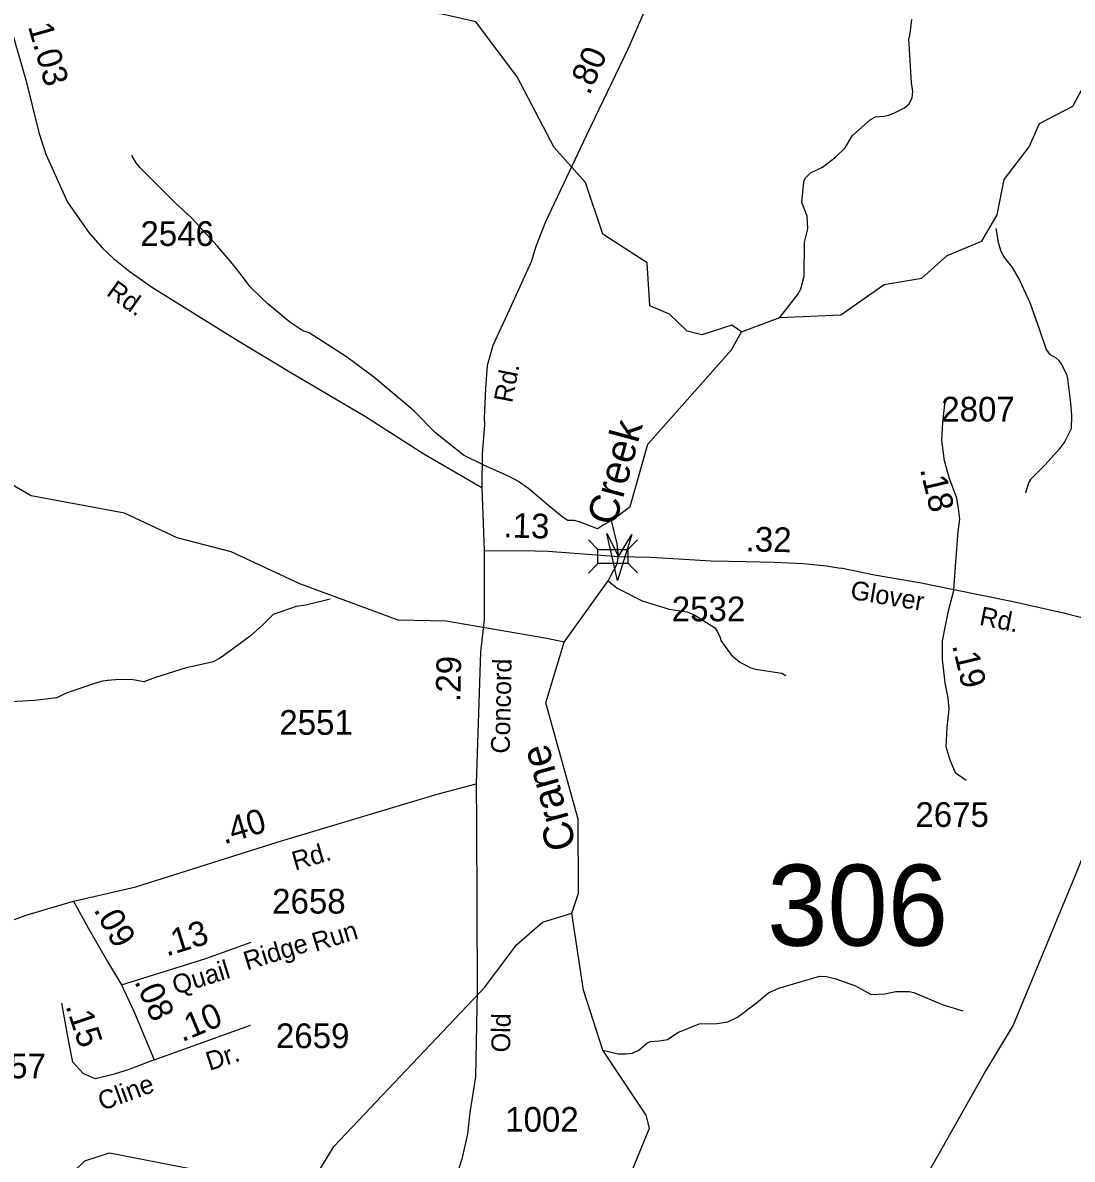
# Model space of a CAD drawing. Extents: x 1473865 to 1648260, y 639067 to 773536.
# Drawn here: x 1551434 to 1556744, y 667690 to 673439 of the extents above; entities that cross this region are included whole.
import ezdxf

# ---------------------------------------------------------------- set-up
doc = ezdxf.new("R2010")
doc.units = 0
for name, color, linetype in [('Exist Hydrographic Creek Single Shore', 7, 'Continuous'), ('Exist Hydrographic Creek Single Shore Label', 7, 'Continuous'), ('Exist Hydrographic Misc Water Feature', 7, 'Continuous'), ('Exist Road Secondary Mileage Hundredths English Label', 7, 'Continuous'), ('Exist Road Secondary Structure Standard Bridge Attributed CELL', 7, 'Continuous'), ('Exist Road Secondary Structure Standard Bridge CELL', 7, 'Continuous'), ('Exist Road Secondary Structure Standard Bridge Number Label', 7, 'Continuous'), ('Exist Road Secondary Type 51 Attributed', 7, 'Continuous'), ('Exist Road Secondary Type 51 Label', 7, 'Continuous'), ('Exist Road Secondary Type 51 Number Label', 7, 'Continuous'), ('Exist Utilities Electrical Transmission Line', 7, 'Continuous')]:
    doc.layers.add(name, color=color, linetype=linetype)

msp = doc.modelspace()

# ---------------------------------------------------------------- linework, layer by layer
at = {"layer": 'Exist Hydrographic Creek Single Shore'}
for p, q in [((1554172.4, 670305.3), (1554085.4, 670323.4)), ((1554063.8, 668889.4), (1554211.3, 668935.7))]:
    msp.add_line(p, q, dxfattribs=at)
for points in [[(1554123, 672807.5), (1553935.4, 673165.7), (1553726.4, 673443.2), (1553556.4, 673481.9), (1553324.4, 673509.6), (1553241.4, 673554), (1553135.4, 673697.3), (1553079.4, 673829.7), (1552890.4, 674027.2), (1552768.5, 674236.4), (1552555.4, 674457.4), (1552482.4, 674583.5), (1552154.5, 674944.7), (1551831.4, 675584.7), (1551686.1, 675837.9), (1551655.2, 675963.3), (1551592.1, 676013.9), (1551494.5, 676431.8), (1551362.4, 676559.2), (1551113.4, 676613.5), (1550907.4, 676732.5)], [(1555070.4, 671875.8), (1555263.5, 671947.4), (1555572.5, 671960.9), (1555791.5, 672114), (1555983.4, 672146.2), (1556110.4, 672261.8), (1556286.5, 672333.7), (1556363.5, 672466.8), (1556399.4, 672646.6), (1556526.5, 672811.5), (1556578.5, 672928.5), (1556746.5, 673017.1), (1556823.5, 673159.9), (1557043.4, 673372.1), (1557481.5, 673698.1), (1557672.5, 673648.3), (1557798.5, 673678.6), (1557883.5, 673834.4), (1557865.7, 674112.6), (1557939.2, 674210.1), (1558074.5, 674332.8), (1558259.5, 674430.8)], [(1554085.4, 670323.4), (1553575.4, 670412.5), (1553333.4, 670417.4), (1552836.4, 670601.4), (1552488.4, 670762.6), (1552214.3, 670833.8), (1551949.4, 670957.3), (1551476.4, 671045.7), (1551087.4, 671270.2), (1550964.3, 671403.9), (1550851.4, 671606.5), (1550744.4, 671726.8), (1550656.3, 671925.5), (1550653.4, 672250.5), (1550520.4, 672853.9), (1550301.4, 673199.7), (1550256.4, 673509.2), (1550159.4, 673727.7), (1550088.4, 673985.2), (1550033.4, 674212.8)], [(1555070.4, 671875.8), (1555021.4, 671909.6), (1554870.4, 671860.2), (1554795.4, 671878.1), (1554705.4, 671965.2), (1554606.5, 672006.6), (1554592.4, 672223.6), (1554369.4, 672369.2), (1554281.5, 672630.3), (1554123, 672807.5)], [(1554172.4, 670305.3), (1554396.2, 670615.8), (1554441.5, 670701.6), (1554447.6, 670738.8), (1554441.6, 670803.2), (1554411.9, 670921.2), (1554507.4, 670991.1), (1554596.4, 671307.7), (1555019.4, 671784.9), (1555070.4, 671875.8)], [(1554211.3, 668935.7), (1554246.4, 669036.7), (1554243.4, 669411), (1554080.5, 669998.5), (1554172.4, 670305.3)], [(1554604.3, 667312.7), (1554582.4, 667464.2), (1554517.4, 667632.9), (1554604.3, 667847.8), (1554588.3, 667913.7), (1554369.6, 668241.2), (1554270.8, 668545.4), (1554211.3, 668935.7)], [(1545869.2, 665457.2), (1546029.2, 665562.3), (1546363.3, 665591.7), (1546740.3, 665718.7), (1547066.3, 665771.2), (1547409.2, 665859.4), (1548036, 665819.7), (1548368.3, 665853.2), (1548861.3, 665984.4), (1549566.3, 666242.6), (1550238.3, 666590.1), (1550751.3, 666888.3), (1551234.3, 667374.3), (1551553.3, 667492.6), (1551748.4, 667682.2), (1551873.3, 667722.4), (1552289.4, 667641.8), (1552916, 667605.3), (1553007.1, 667754.7), (1553771.4, 668560.5), (1553932.4, 668773.9), (1554063.8, 668889.4)]]:
    msp.add_lwpolyline(points, dxfattribs=at)
at = {"layer": 'Exist Hydrographic Misc Water Feature'}
for points in [[(1555263.5, 671947.4), (1555357.9, 672069), (1555370.2, 672092.8), (1555386.9, 672156.6), (1555388.8, 672328.6), (1555405.6, 672396.4), (1555402.3, 672460.5), (1555375, 672528.8), (1555384, 672616.7), (1555388.2, 672640.7), (1555396.4, 672656.5), (1555418.7, 672680.3), (1555481, 672707.6), (1555545.6, 672758.9), (1555594.2, 672806.3), (1555630.9, 672865.9), (1555723.8, 672948.8), (1555748, 672962.5), (1555792.1, 672966), (1555814.1, 672971.8), (1555840.3, 672981.5), (1555894.5, 673008.8), (1555916.8, 673026.6), (1555933.2, 673058.3), (1555937.5, 673090.3), (1555930, 673134.4), (1555916.4, 673358.6), (1555920.5, 673366.5), (1555924.9, 673398.5), (1555931.5, 673454.4)], [(1554095.8, 670994.4), (1553995.2, 671081.8), (1553941.8, 671119), (1553894.1, 671143.8), (1553767, 671201.3), (1553663.8, 671251), (1553521.4, 671363.8), (1553413.2, 671475.1), (1553365.8, 671516.3), (1553209.9, 671646.7), (1553116.9, 671715.8), (1553071.3, 671748.7), (1552883.2, 671869.9), (1552851.4, 671880.4), (1552786, 671923.5), (1552673.4, 672016.9), (1552643.8, 672045.4), (1552584.7, 672102.4), (1552551.3, 672149), (1552494.5, 672219.9), (1552420, 672309.2), (1552288.2, 672451.4), (1552205.3, 672527), (1552028, 672705.3), (1552008.4, 672729.5), (1551988.9, 672760.3), (1551987, 672768.5)], [(1556356.6, 672398.7), (1556369.2, 672329.2), (1556380.8, 672289.1), (1556396.4, 672256.9), (1556439.8, 672200.4), (1556477.1, 672135.9), (1556529.9, 672023.3), (1556576.4, 671890.8), (1556611.3, 671786.4), (1556629, 671762.1), (1556658.8, 671745.8), (1556674.7, 671731.6), (1556688.5, 671713.4), (1556713.9, 671661.1), (1556719.6, 671637.1), (1556732.5, 671528.9), (1556740.8, 671453.5), (1556738.9, 671384.8), (1556706.2, 671321.2), (1556677.7, 671281.5), (1556606.9, 671202.3), (1556532, 671129.2), (1556521.8, 671111.3), (1556507.2, 671059.5)], [(1554411.9, 670921.2), (1554370, 670897.2), (1554342.6, 670879.3), (1554290.1, 670899.6), (1554248.4, 670913.9), (1554223.4, 670921.1), (1554192.4, 670921.1), (1554162.6, 670940.2), (1554095.8, 670994.4)], [(1554396.2, 670615.8), (1554441.1, 670579.5), (1554568.4, 670514), (1554704, 670472.4), (1554795.9, 670459.4), (1554834.9, 670442.5), (1554933, 670379.7), (1554946.9, 670361.6), (1554962.5, 670329.4), (1554966.3, 670313.4), (1555017.6, 670240.8), (1555061.2, 670204.2), (1555116.8, 670175.6), (1555140.8, 670169.3), (1555273.8, 670148.1), (1555295, 670137.6)], [(1552989.9, 670523.6), (1552865.5, 670493.2), (1552817.3, 670486), (1552700.8, 670445.7), (1552647.8, 670392.6), (1552584.9, 670335.6), (1552451.3, 670238.2), (1552428.9, 670222.2), (1552396.8, 670206.5), (1552316.4, 670187.6), (1552260.3, 670176.4), (1552105.3, 670127), (1552047, 670104.4), (1551983.3, 670117.2), (1551903.3, 670114.7), (1551863.2, 670111.4), (1551839.1, 670107.7), (1551806.9, 670100.2), (1551654, 670048.3), (1551605.6, 670024.7), (1551493.3, 670010.6), (1551223, 669994.7)], [(1554369.6, 668241.2), (1554447, 668223.2), (1554487, 668222.8), (1554519, 668226.3), (1554551.2, 668242), (1554591.6, 668277.5), (1554607.7, 668285.3), (1554655.8, 668288.8), (1554695.9, 668296.3), (1554748.3, 668331.7), (1554856.8, 668374.4), (1554944.9, 668377.4), (1555001, 668384.7), (1555049.3, 668408.2), (1555146.2, 668481.1), (1555206.8, 668532.4), (1555259.4, 668554.9), (1555465.7, 668615.4), (1555499.8, 668615), (1555547.7, 668602.4), (1555619.3, 668577.6), (1555643.3, 668569.3), (1555726.8, 668524.3), (1555794.9, 668527.5), (1555851, 668538.9), (1555919, 668538.1), (1555943, 668533.8), (1556086.4, 668472.1), (1556190.1, 668440.9)]]:
    msp.add_lwpolyline(points, dxfattribs=at)
at = {"layer": 'Exist Road Secondary Structure Standard Bridge Attributed CELL'}
msp.add_lwpolyline([(1554515.3, 670849.7), (1554442.7, 670617), (1554389.2, 670854.9), (1554447.6, 670738.8)], close=True, dxfattribs=at)
at = {"layer": 'Exist Road Secondary Structure Standard Bridge CELL'}
for p, q in [((1554295.5, 670823.4), (1554344.3, 670774.6)), ((1554495.4, 670774.3), (1554544.2, 670823.1)), ((1554295.5, 670655.2), (1554344.3, 670704)), ((1554495.4, 670705.3), (1554544.2, 670656.5))]:
    msp.add_line(p, q, dxfattribs=at)
msp.add_lwpolyline([(1554344.3, 670774.6), (1554495.4, 670774.6), (1554495.4, 670704), (1554344.3, 670704)], close=True, dxfattribs=at)
at = {"layer": 'Exist Road Secondary Type 51 Attributed'}
msp.add_line((1553756.9, 671087.2), (1553769.2, 670769.7), dxfattribs=at)
for points in [[(1550940.2, 675288.3), (1550975.2, 675029.7), (1551015.3, 674814.9), (1551076, 674530), (1551123.4, 674346.4), (1551261.9, 673777.8), (1551375.7, 673405.7), (1551449, 673150.3), (1551515.1, 672884.1), (1551550.9, 672773.3), (1551660.5, 672531.4), (1551765.7, 672379.4), (1551836.1, 672300.2), (1551893.1, 672247), (1551977.9, 672179.4), (1552090.4, 672099.3), (1552519.2, 671833.4), (1552789.5, 671669.1), (1553167.9, 671447.1), (1553463.3, 671258.5), (1553587.7, 671185), (1553756.9, 671087.2)], [(1554841.1, 674571.4), (1554828.6, 674439.1), (1554807, 674259.3), (1554779.6, 674081.3), (1554750, 673915.6), (1554717, 673817.9), (1554660, 673690.4), (1554588.3, 673517.1), (1554495.1, 673305.1), (1554285.5, 672870.8), (1554078.9, 672432.2), (1554030, 672307.7), (1554005.5, 672229.4), (1553905.7, 672006.6), (1553812.1, 671806.6), (1553783, 671704.4), (1553775.3, 671591.1), (1553768.4, 671438.2), (1553769.9, 671404.6), (1553758.4, 671257.7), (1553756.9, 671087.2)], [(1556144.6, 670572.3), (1556154, 670710.6), (1556166.2, 670865.9), (1556174.4, 670927.2), (1556168.3, 670982.3), (1556160.1, 671033.4), (1556123.4, 671133.5), (1556096.8, 671223.4), (1556084.6, 671327.6), (1556088.6, 671415.5), (1556100.9, 671523.8)], [(1553769.2, 670769.7), (1553767.6, 670420.5), (1553749.2, 670254.6), (1553727.6, 669589.4)], [(1553769.2, 670769.7), (1554026.6, 670767.6), (1554092.2, 670765.6), (1554447.6, 670738.8)], [(1554447.6, 670738.8), (1554613.5, 670736.1), (1554917.5, 670717.3), (1555093.7, 670713.6), (1555235.7, 670710.3), (1555381.6, 670703), (1555499.7, 670691.8), (1555561.7, 670682.2), (1555581.6, 670679.1), (1555743.4, 670645.6), (1555971.2, 670607.4), (1556144.6, 670572.3)], [(1556144.6, 670572.3), (1556114.1, 670455.1), (1556085.8, 670313.1), (1556085.8, 670218.5), (1556099.9, 670100.2), (1556114.1, 670022.1), (1556118.9, 669967.7), (1556109.4, 669873.1), (1556104.7, 669778.4), (1556123.6, 669709.8), (1556151.9, 669645.9), (1556206.3, 669608.1)], [(1556144.6, 670572.3), (1556436.5, 670513.2), (1556700, 670454.6), (1556786, 670431.9), (1556873.5, 670387.1), (1556978.9, 670314.1), (1557364, 669964.4), (1557463.3, 669887.3), (1557525.2, 669858.9)], [(1551691.1, 668995), (1552005.7, 669067.7), (1552721.2, 669294.4), (1553529.9, 669537.2), (1553727.6, 669589.4)], [(1553727.6, 669589.4), (1553729.3, 669385.9), (1553733.3, 668545.3), (1553725.3, 668107.7), (1553696.1, 667926.1), (1553684.1, 667818.3), (1553655.7, 667691), (1553600.4, 667525.1), (1553546.8, 667366), (1553485.4, 667217), (1553407.3, 667016.9), (1553360.3, 666852), (1553314.9, 666687.6), (1553265.1, 666524.9), (1553177.7, 666281.9), (1553076, 666070.6), (1552984.7, 665900.4), (1552888.1, 665745.9), (1552797.7, 665619.7), (1552625.7, 665437.1), (1552496.6, 665283.9)], [(1550597.3, 668678.5), (1550696.8, 668698.9), (1550807.3, 668718.5), (1551207.5, 668836.9), (1551456.3, 668926.1), (1551691.1, 668995)], [(1551691.1, 668995), (1551767.3, 668857.2), (1551862, 668691), (1551932.9, 668572.2)], [(1551932.9, 668572.2), (1552360.7, 668706.3), (1552589.4, 668788.7)], [(1551932.9, 668572.2), (1551999.7, 668430), (1552098.5, 668192.5)], [(1552098.5, 668192.5), (1551967.7, 668142.3), (1551885.3, 668116.4), (1551800.5, 668096.3), (1551739, 668124.6), (1551687.4, 668181.2), (1551666.5, 668283.3), (1551632.1, 668479)], [(1552098.5, 668192.5), (1552271.9, 668255.3), (1552586.6, 668368.5)]]:
    msp.add_lwpolyline(points, dxfattribs=at)
at = {"layer": 'Exist Utilities Electrical Transmission Line'}
msp.add_lwpolyline([(1558364.7, 673697.6), (1558257.3, 673196.7), (1558185.9, 672871.4), (1558114.9, 672594.1), (1558017.1, 672239.1), (1557903.8, 671942.2), (1557733.5, 671534.1), (1557585.3, 671141.7), (1557425.3, 670769.3), (1557266.9, 670367.1), (1557174.5, 670142.1), (1556979.4, 669674), (1556765.7, 669142.3), (1556554.2, 668632.7), (1556445.4, 668367.8), (1556306.9, 668139.2), (1556068.2, 667717.9), (1555803.4, 667254.6)], dxfattribs=at)

# ---------------------------------------------------------------- texts
at = {"layer": 'Exist Hydrographic Creek Single Shore Label'}
for s, rotation, p in [('Creek', 74.79726, (1554431.8, 670888.3)), ('Crane', 105.49806, (1554236.4, 669274))]:
    msp.add_text(s, height=150, rotation=rotation, dxfattribs=at).set_placement(p)
at = {"layer": 'Exist Road Secondary Mileage Hundredths English Label'}
for s, rotation, p in [('1.03', 286.00866, (1551459.5, 673420.8)), ('.80', 66.34443, (1554300.5, 673068.1)), ('.18', 283.55931, (1555972.9, 671180.1)), ('.13', 358.23658, (1553864.4, 670836)), ('.32', 358.77763, (1555090.2, 670765.2)), ('.19', 283.55931, (1556135.4, 670289)), ('.29', 88.75601, (1553647.6, 670002.3)), ('.40', 16.72478, (1552452.3, 669282.4)), ('.09', 298.76117, (1551790.4, 668952.7)), ('.13', 17.1918, (1552161.5, 668715.4)), ('.08', 294.12638, (1551997.1, 668589.3)), ('.15', 288.52068, (1551649.3, 668465.3)), ('.10', 22.83159, (1552240.4, 668281.7))]:
    msp.add_text(s, height=125, rotation=rotation, dxfattribs=at).set_placement(p)
at = {"layer": 'Exist Road Secondary Structure Standard Bridge Number Label'}
msp.add_text('306', height=410.1, dxfattribs=at).set_placement((1555200.3, 668770.3))
at = {"layer": 'Exist Road Secondary Type 51 Label'}
for s, rotation, p in [('Rd.', 324.53244, (1551852.1, 672064.3)), ('Rd.', 78.97308, (1553910, 671512.3)), ('Glover', 350.47424, (1555616.8, 670525.2)), ('Rd.', 348.55131, (1556269.1, 670393.9)), ('Concord', 88.75601, (1553897.2, 669741.2)), ('Rd.', 16.18583, (1552811.7, 669150.3)), ('Run', 17.13134, (1552914.6, 668739)), ('Ridge', 17.1918, (1552568.4, 668644.8)), ('Quail', 17.1918, (1552207.4, 668521.9)), ('Old', 88.83411, (1553899.2, 668229.8)), ('Dr.', 18.19372, (1552379.1, 668136.7)), ('Cline', 20.05999, (1551835.2, 667934.5))]:
    msp.add_text(s, height=95, rotation=rotation, dxfattribs=at).set_placement(p)
at = {"layer": 'Exist Road Secondary Type 51 Number Label'}
for s, p in [('2546', (1552029.2, 672309.7)), ('2807', (1556081.2, 671421.6)), ('2532', (1554717.6, 670411.4)), ('2551', (1552731.9, 669837.1)), ('2675', (1555950.2, 669371.1)), ('2658', (1552695.7, 668932.8)), ('2659', (1552714.9, 668252.1)), ('2657', (1551179.3, 668099.5)), ('1002', (1553874.8, 667829.3))]:
    msp.add_text(s, height=125, dxfattribs=at).set_placement(p)

doc.saveas('drawing.dxf')
